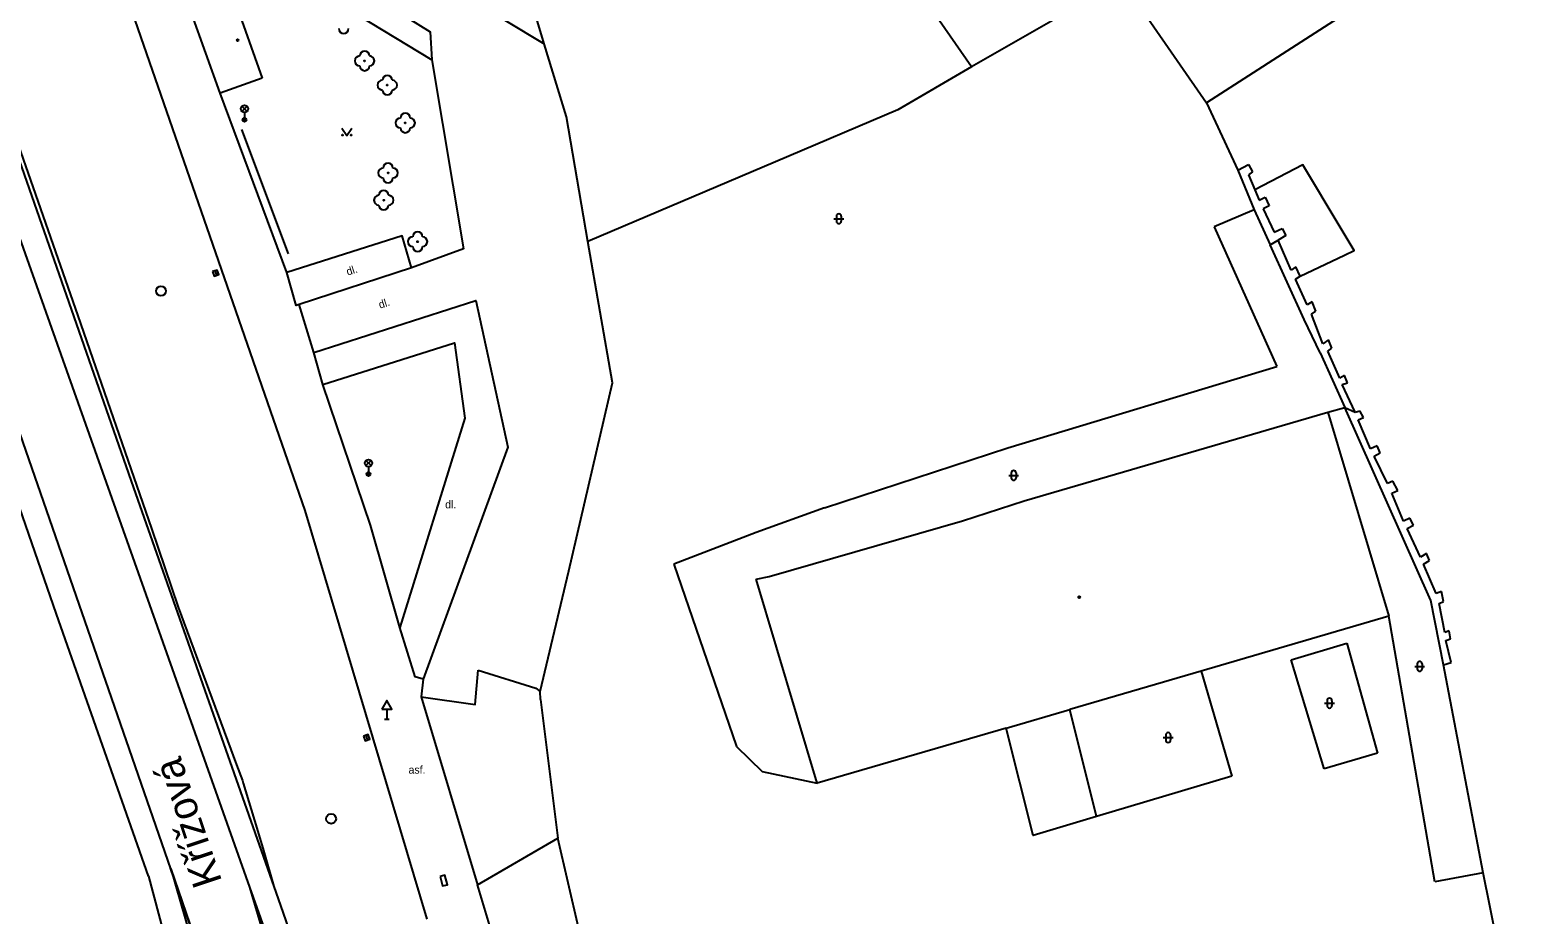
# Model space of a CAD drawing. Extents: x -599770 to -598493, y -1162076 to -1159209.
# Drawn here: x -599224.4 to -599147.3, y -1161305.8 to -1161260.5 of the extents above; entities that cross this region are included whole.
import ezdxf

# ---------------------------------------------------------------- set-up
doc = ezdxf.new("R2010")
doc.units = 0
doc.layers.add('Podklad', color=7, linetype='Continuous')

msp = doc.modelspace()

# ---------------------------------------------------------------- linework, layer by layer
at = {"layer": 'Podklad'}
for p, q in [((-599213.553, -1161264.7), (-599213.288, -1161264.435)), ((-599213.553, -1161264.435), (-599213.288, -1161264.7)), ((-599213.42, -1161264.755), (-599213.42, -1161265.13)), ((-599183.283, -1161270.188), (-599182.783, -1161270.188)), ((-599183.158, -1161270.063), (-599183.158, -1161270.313)), ((-599182.908, -1161270.063), (-599182.908, -1161270.313)), ((-599214.932, -1161272.852), (-599214.848, -1161273.088)), ((-599207.212, -1161282.81), (-599206.947, -1161282.545)), ((-599207.212, -1161282.545), (-599206.947, -1161282.81)), ((-599207.08, -1161282.865), (-599207.08, -1161283.24)), ((-599174.343, -1161283.308), (-599173.843, -1161283.308)), ((-599174.218, -1161283.183), (-599174.218, -1161283.433)), ((-599173.968, -1161283.183), (-599173.968, -1161283.433)), ((-599153.458, -1161292.943), (-599153.458, -1161293.193)), ((-599153.208, -1161292.943), (-599153.208, -1161293.193)), ((-599153.583, -1161293.068), (-599153.083, -1161293.068)), ((-599206.14, -1161295.251), (-599206.14, -1161295.76)), ((-599158.193, -1161294.948), (-599157.693, -1161294.948)), ((-599158.068, -1161294.823), (-599158.068, -1161295.073)), ((-599157.818, -1161294.823), (-599157.818, -1161295.073)), ((-599206.265, -1161295.76), (-599206.015, -1161295.76)), ((-599207.212, -1161296.602), (-599207.128, -1161296.838)), ((-599166.443, -1161296.708), (-599165.943, -1161296.708)), ((-599166.318, -1161296.583), (-599166.318, -1161296.833)), ((-599166.068, -1161296.583), (-599166.068, -1161296.833))]:
    msp.add_line(p, q, dxfattribs=at)
for points in [[(-599242.28, -1161232.13), (-599236.75, -1161230.76), (-599235.67, -1161234.62), (-599233.05, -1161244.03), (-599229.93, -1161252.99), (-599227.25, -1161260.65), (-599219.1, -1161283.94), (-599211.92, -1161304.32), (-599211.46, -1161305.63)], [(-599218.33, -1161303.79), (-599223.03, -1161290.4), (-599226.67, -1161279.96), (-599232.838, -1161262.313), (-599235.39, -1161255.01), (-599238.64, -1161245.79), (-599242.28, -1161232.13)], [(-599235.81, -1161239.19), (-599234.34, -1161244.43), (-599231.21, -1161253.44), (-599213.17, -1161304.35)], [(-599176.24, -1161262.43), (-599191.09, -1161241.08)], [(-599198.29, -1161294.76), (-599198.31, -1161294.35), (-599196.84, -1161288.18), (-599194.61, -1161278.57), (-599195.86, -1161271.36), (-599196.96, -1161264.98), (-599198.09, -1161261.25), (-599199.18, -1161257.63), (-599202.62, -1161249.31)], [(-599140.89, -1161249.24), (-599164.23, -1161264.27)], [(-599222.15, -1161251.09), (-599221.09, -1161254.07), (-599210.33, -1161285.1), (-599204.1, -1161305.99)], [(-599218.51, -1161252.39), (-599217.92, -1161251.92), (-599203.92, -1161260.64), (-599203.85, -1161262.06)], [(-599218.22, -1161253.35), (-599203.85, -1161262.06)], [(-599217.19, -1161303.41), (-599234.12, -1161254.56)], [(-599208.16, -1161255.19), (-599198.09, -1161261.25)], [(-599168.73, -1161257.76), (-599164.23, -1161264.27)], [(-599213.93, -1161259.01), (-599212.51, -1161263)], [(-599214.67, -1161263.77), (-599216.13, -1161259.68)], [(-599227.03, -1161260.589), (-599226.79, -1161261.274), (-599225.587, -1161264.712), (-599225.508, -1161264.94), (-599221.934, -1161275.156), (-599218.176, -1161286.023), (-599216.81, -1161290.04)], [(-599172.08, -1161260.04), (-599176.24, -1161262.43)], [(-599203.85, -1161262.06), (-599202.23, -1161271.73), (-599204.88, -1161272.69)], [(-599176.24, -1161262.43), (-599180.01, -1161264.62)], [(-599212.51, -1161263), (-599214.67, -1161263.77)], [(-599211.26, -1161272.93), (-599214.67, -1161263.77)], [(-599164.23, -1161264.27), (-599162.63, -1161267.7)], [(-599180.01, -1161264.62), (-599186.27, -1161267.28), (-599195.86, -1161271.36)], [(-599213.58, -1161265.62), (-599211.18, -1161271.98)], [(-599208.44, -1161265.565), (-599208.19, -1161265.94), (-599207.94, -1161265.565)], [(-599162.63, -1161267.7), (-599162.08, -1161267.41)], [(-599162.08, -1161267.41), (-599161.88, -1161267.79)], [(-599157.18, -1161272.05), (-599156.68, -1161271.81), (-599157.39, -1161270.62), (-599159.3, -1161267.44), (-599161.76, -1161268.71)], [(-599162.63, -1161267.7), (-599161.8, -1161269.74)], [(-599161.88, -1161267.79), (-599162.08, -1161267.94)], [(-599162.08, -1161267.94), (-599161.76, -1161268.71), (-599161.54, -1161269.24)], [(-599161.54, -1161269.24), (-599161.23, -1161269.09)], [(-599161.23, -1161269.09), (-599161.02, -1161269.53)], [(-599161.8, -1161269.74), (-599163.84, -1161270.61)], [(-599161.8, -1161269.74), (-599160.98, -1161271.52)], [(-599161.02, -1161269.53), (-599161.34, -1161269.68)], [(-599161.34, -1161269.68), (-599160.78, -1161270.87)], [(-599163.84, -1161270.61), (-599160.63, -1161277.75)], [(-599204.88, -1161272.69), (-599205.36, -1161271.07), (-599211.26, -1161272.93)], [(-599160.98, -1161271.52), (-599160.57, -1161271.28)], [(-599160.78, -1161270.87), (-599160.37, -1161270.68)], [(-599160.18, -1161271.04), (-599160.57, -1161271.28)], [(-599159.91, -1161272.82), (-599160.57, -1161271.28)], [(-599160.37, -1161270.68), (-599160.18, -1161271.04)], [(-599159.23, -1161275.34), (-599160.98, -1161271.52)], [(-599159.45, -1161273.13), (-599157.18, -1161272.05)], [(-599210.63, -1161274.57), (-599210.78, -1161274.63), (-599211.26, -1161272.93)], [(-599204.88, -1161272.69), (-599210.63, -1161274.57)], [(-599159.67, -1161272.65), (-599159.91, -1161272.82)], [(-599159.45, -1161273.13), (-599159.67, -1161272.65)], [(-599159.68, -1161273.27), (-599159.45, -1161273.13)], [(-599159.09, -1161274.59), (-599159.68, -1161273.27)], [(-599209.88, -1161277.03), (-599201.59, -1161274.36), (-599199.95, -1161281.86), (-599204.28, -1161293.73), (-599204.69, -1161293.61), (-599205.48, -1161291.08)], [(-599158.83, -1161274.44), (-599159.09, -1161274.59)], [(-599158.65, -1161274.92), (-599158.83, -1161274.44)], [(-599209.88, -1161277.03), (-599210.63, -1161274.57)], [(-599158.87, -1161275.07), (-599158.65, -1161274.92)], [(-599158.29, -1161276.58), (-599158.87, -1161275.07)], [(-599158.42, -1161277.05), (-599159.23, -1161275.34)], [(-599209.42, -1161278.66), (-599202.69, -1161276.53), (-599202.16, -1161280.39), (-599205.48, -1161291.08)], [(-599158, -1161276.37), (-599158.29, -1161276.58)], [(-599158.03, -1161276.95), (-599157.82, -1161276.8)], [(-599157.82, -1161276.8), (-599158, -1161276.37)], [(-599209.42, -1161278.66), (-599209.88, -1161277.03)], [(-599158.42, -1161277.05), (-599157.16, -1161279.84)], [(-599157.41, -1161278.33), (-599158.03, -1161276.95)], [(-599174.39, -1161281.9), (-599160.63, -1161277.75)], [(-599157.17, -1161278.21), (-599157.41, -1161278.33)], [(-599157.02, -1161278.57), (-599157.17, -1161278.21)], [(-599205.48, -1161291.08), (-599206.98, -1161285.86), (-599209.42, -1161278.66)], [(-599157.29, -1161278.66), (-599157.02, -1161278.57)], [(-599156.63, -1161280.08), (-599157.29, -1161278.66)], [(-599158.02, -1161280.07), (-599157.16, -1161279.84)], [(-599157.16, -1161279.84), (-599156.63, -1161280.08)], [(-599152.77, -1161289.71), (-599157.16, -1161279.84)], [(-599173.56, -1161284.61), (-599158.02, -1161280.07)], [(-599158.02, -1161280.07), (-599154.91, -1161290.5)], [(-599156.63, -1161280.08), (-599156.4, -1161280.01)], [(-599156.47, -1161280.46), (-599156.21, -1161280.34)], [(-599155.84, -1161281.95), (-599156.47, -1161280.46)], [(-599156.21, -1161280.34), (-599156.4, -1161280.01)], [(-599183.76, -1161284.97), (-599174.39, -1161281.9)], [(-599155.51, -1161281.8), (-599155.84, -1161281.95)], [(-599155.66, -1161282.32), (-599155.35, -1161282.15)], [(-599155.35, -1161282.15), (-599155.51, -1161281.8)], [(-599154.97, -1161283.73), (-599155.66, -1161282.32)], [(-599154.7, -1161283.6), (-599154.97, -1161283.73)], [(-599154.45, -1161284.08), (-599154.7, -1161283.6)], [(-599154.76, -1161284.22), (-599154.45, -1161284.08)], [(-599154.16, -1161285.64), (-599154.76, -1161284.22)], [(-599183.76, -1161284.97), (-599187.25, -1161286.22)], [(-599176.7, -1161285.63), (-599173.56, -1161284.61)], [(-599186.6, -1161288.47), (-599176.7, -1161285.63)], [(-599153.84, -1161285.49), (-599154.16, -1161285.64)], [(-599153.98, -1161286.02), (-599153.65, -1161285.85)], [(-599153.29, -1161287.48), (-599153.98, -1161286.02)], [(-599153.65, -1161285.85), (-599153.84, -1161285.49)], [(-599187.25, -1161286.22), (-599191.47, -1161287.85)], [(-599152.99, -1161287.3), (-599153.29, -1161287.48)], [(-599152.83, -1161287.66), (-599152.99, -1161287.3)], [(-599191.47, -1161287.85), (-599188.26, -1161297.16)], [(-599153.14, -1161287.85), (-599152.83, -1161287.66)], [(-599152.49, -1161289.35), (-599153.14, -1161287.85)], [(-599187.25, -1161288.61), (-599186.6, -1161288.47)], [(-599184.14, -1161299.04), (-599187.25, -1161288.61)], [(-599152.12, -1161292.99), (-599152.77, -1161289.71)], [(-599152.22, -1161289.25), (-599152.49, -1161289.35)], [(-599152.34, -1161289.86), (-599152.12, -1161289.75)], [(-599152.05, -1161291.34), (-599152.34, -1161289.86)], [(-599152.12, -1161289.75), (-599152.22, -1161289.25)], [(-599216.81, -1161290.04), (-599213.822, -1161298.1), (-599213.526, -1161298.898), (-599213.484, -1161299.037), (-599212.796, -1161301.338), (-599212.453, -1161302.486), (-599211.922, -1161304.32)], [(-599154.91, -1161290.5), (-599164.51, -1161293.32)], [(-599152.55, -1161304.08), (-599154.91, -1161290.5)], [(-599151.82, -1161291.26), (-599152.05, -1161291.34)], [(-599151.75, -1161291.66), (-599151.82, -1161291.26)], [(-599159.9, -1161292.73), (-599157.05, -1161291.88)], [(-599157.05, -1161291.88), (-599155.49, -1161297.51)], [(-599152, -1161291.74), (-599151.75, -1161291.66)], [(-599151.72, -1161292.87), (-599152, -1161291.74)], [(-599158.22, -1161298.31), (-599159.9, -1161292.73)], [(-599152.12, -1161292.99), (-599151.72, -1161292.87)], [(-599150.09, -1161303.62), (-599152.12, -1161292.99)], [(-599204.39, -1161294.63), (-599201.62, -1161295.01), (-599201.47, -1161293.27)], [(-599204.28, -1161293.73), (-599204.39, -1161294.63)], [(-599201.47, -1161293.27), (-599198.52, -1161294.18), (-599198.31, -1161294.35)], [(-599164.51, -1161293.32), (-599171.22, -1161295.27)], [(-599164.51, -1161293.32), (-599162.94, -1161298.68)], [(-599204.39, -1161294.63), (-599201.5, -1161304.24)], [(-599198.29, -1161294.76), (-599197.4, -1161301.85)], [(-599174.47, -1161296.22), (-599171.22, -1161295.27)], [(-599169.85, -1161300.75), (-599171.22, -1161295.27)], [(-599174.47, -1161296.22), (-599184.14, -1161299.04)], [(-599169.85, -1161300.75), (-599173.1, -1161301.72), (-599174.47, -1161296.22)], [(-599188.26, -1161297.16), (-599186.95, -1161298.45)], [(-599155.49, -1161297.51), (-599158.22, -1161298.31)], [(-599186.95, -1161298.45), (-599184.14, -1161299.04)], [(-599162.94, -1161298.68), (-599169.85, -1161300.75)], [(-599198.1, -1161314.28), (-599198.78, -1161314.15), (-599198.7, -1161313.61), (-599201.5, -1161304.24), (-599197.4, -1161301.85)], [(-599196.35, -1161306.41), (-599197.4, -1161301.85)], [(-599218.33, -1161303.79), (-599217.02, -1161308.74), (-599216.27, -1161312.37), (-599216.11, -1161314.22)], [(-599216.03, -1161306.79), (-599217.196, -1161303.386)], [(-599217.19, -1161303.41), (-599216.19, -1161306.84)], [(-599217.19, -1161303.41), (-599216.03, -1161306.79)], [(-599150.09, -1161303.62), (-599152.55, -1161304.08)], [(-599147.95, -1161314.17), (-599150.09, -1161303.62)], [(-599213.17, -1161304.35), (-599212.04, -1161307.52)], [(-599213.17, -1161304.35), (-599212.21, -1161307.57)], [(-599211.46, -1161305.63), (-599210.37, -1161308.78), (-599209.14, -1161311.88), (-599207.76, -1161314.91), (-599206.24, -1161317.88), (-599204.26, -1161320.91), (-599201.71, -1161323.71), (-599197.71, -1161326.78), (-599194.46, -1161328.55), (-599190.31, -1161330.36)]]:
    msp.add_lwpolyline(points, dxfattribs=at)
for points in [[(-599215.05, -1161272.894), (-599214.966, -1161273.13), (-599214.73, -1161273.046), (-599214.814, -1161272.81)], [(-599206.39, -1161295.251), (-599205.89, -1161295.251), (-599206.14, -1161294.818)], [(-599207.33, -1161296.644), (-599207.246, -1161296.88), (-599207.01, -1161296.796), (-599207.094, -1161296.56)], [(-599203.411, -1161303.807), (-599203.291, -1161304.293), (-599203.049, -1161304.233), (-599203.169, -1161303.747)]]:
    msp.add_lwpolyline(points, close=True, dxfattribs=at)
for centre, radius in [((-599213.77, -1161261.06), 0.045), ((-599213.77, -1161261.06), 0.0199), ((-599207.28, -1161262.12), 0.025), ((-599206.12, -1161263.36), 0.025), ((-599213.42, -1161264.567), 0.188), ((-599213.42, -1161265.13), 0.1), ((-599213.42, -1161265.13), 0.0723), ((-599213.42, -1161265.13), 0.0438), ((-599208.415, -1161265.915), 0.025), ((-599207.965, -1161265.915), 0.025), ((-599205.2, -1161265.29), 0.025), ((-599206.08, -1161267.85), 0.025), ((-599206.3, -1161269.24), 0.025), ((-599204.57, -1161271.36), 0.025), ((-599217.69, -1161273.88), 0.25), ((-599207.08, -1161282.677), 0.188), ((-599207.08, -1161283.24), 0.1), ((-599207.08, -1161283.24), 0.0723), ((-599207.08, -1161283.24), 0.0438), ((-599170.74, -1161289.53), 0.045), ((-599170.74, -1161289.53), 0.0199), ((-599208.99, -1161300.86), 0.25)]:
    msp.add_circle(centre, radius, dxfattribs=at)
for centre, radius, start, end in [((-599208.35, -1161260.47), 0.25, 180, 0), ((-599207.53, -1161262.12), 0.25, 90, 270), ((-599207.28, -1161261.87), 0.25, 0, 180), ((-599207.03, -1161262.12), 0.25, 270, 90), ((-599207.28, -1161262.37), 0.25, 180, 0), ((-599206.12, -1161263.11), 0.25, 0, 180), ((-599206.37, -1161263.36), 0.25, 90, 270), ((-599206.12, -1161263.61), 0.25, 180, 0), ((-599205.87, -1161263.36), 0.25, 270, 90), ((-599205.45, -1161265.29), 0.25, 90, 270), ((-599205.2, -1161265.04), 0.25, 0, 180), ((-599204.95, -1161265.29), 0.25, 270, 90), ((-599205.2, -1161265.54), 0.25, 180, 0), ((-599206.08, -1161267.6), 0.25, 0, 180), ((-599206.33, -1161267.85), 0.25, 90, 270), ((-599206.08, -1161268.1), 0.25, 180, 0), ((-599205.83, -1161267.85), 0.25, 270, 90), ((-599206.55, -1161269.24), 0.25, 90, 270), ((-599206.3, -1161268.99), 0.25, 0, 180), ((-599206.05, -1161269.24), 0.25, 270, 90), ((-599206.3, -1161269.49), 0.25, 180, 0), ((-599183.033, -1161270.063), 0.125, 0, 180), ((-599183.033, -1161270.313), 0.125, 180, 0), ((-599204.82, -1161271.36), 0.25, 90, 270), ((-599204.57, -1161271.11), 0.25, 0, 180), ((-599204.32, -1161271.36), 0.25, 270, 90), ((-599204.57, -1161271.61), 0.25, 180, 0), ((-599174.093, -1161283.183), 0.125, 0, 180), ((-599174.093, -1161283.433), 0.125, 180, 0), ((-599153.333, -1161292.943), 0.125, 0, 180), ((-599153.333, -1161293.193), 0.125, 180, 0), ((-599157.943, -1161294.823), 0.125, 0, 180), ((-599157.943, -1161295.073), 0.125, 180, 0), ((-599166.193, -1161296.583), 0.125, 0, 180), ((-599166.193, -1161296.833), 0.125, 180, 0)]:
    msp.add_arc(centre, radius, start, end, dxfattribs=at)

# ---------------------------------------------------------------- texts
for s, height, rotation, p in [('dl.', 0.4, 18.11, (-599208.14, -1161273.1)), ('dl.', 0.4, 18.11, (-599206.49, -1161274.79)), ('Křížová', 1.5, 108.42767, (-599214.553, -1161304.065))]:
    msp.add_text(s, height=height, rotation=rotation, dxfattribs=at).set_placement(p)
for s, p in [('dl.', (-599203.16, -1161284.99)), ('asf.', (-599205.03, -1161298.554))]:
    msp.add_text(s, height=0.4, dxfattribs=at).set_placement(p)

doc.saveas('drawing.dxf')
